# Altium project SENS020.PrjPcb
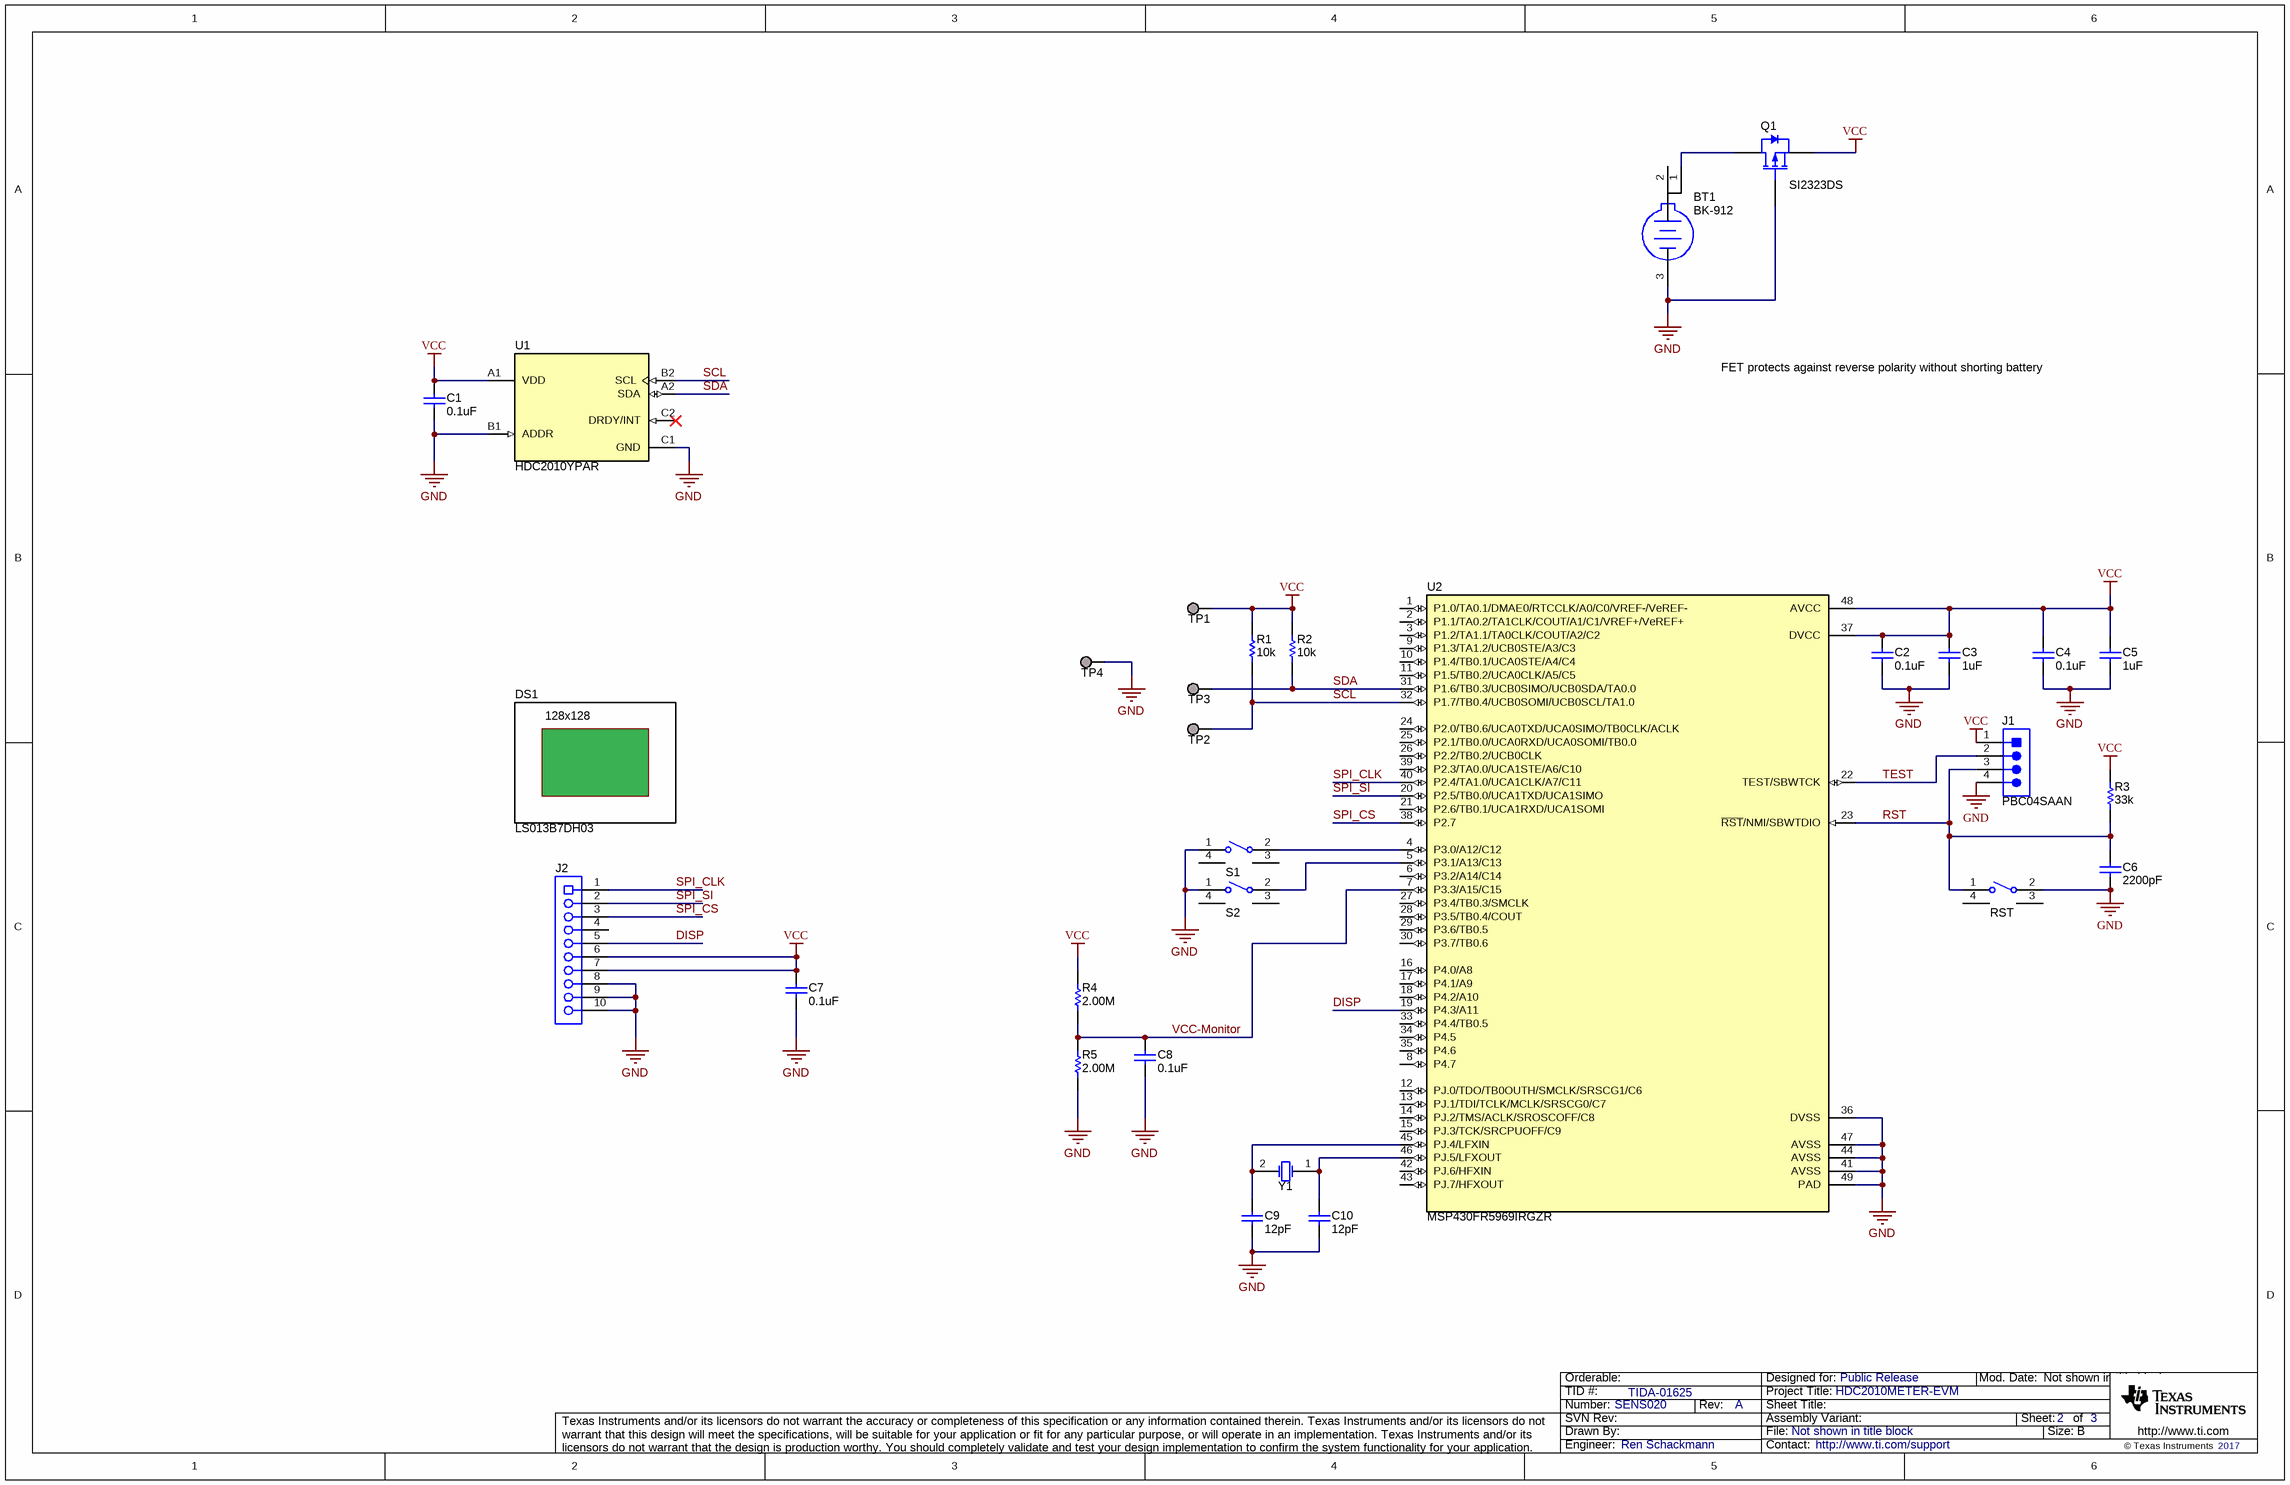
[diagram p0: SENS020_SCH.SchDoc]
TID: TIDA-01625; TechSupport: http://www.ti.com/support; SCH_Rev: A; PRJ_Title: HDC2010METER-EVM; PRJ_Number: SENS020; PRJ_Engineer: Ren Schackmann; PRJ_Customer: Public Release; PCB_Rev: A; PCB_Layout: Ren Schackmann; CopyrightYear: 2017
2 sheets, 51 parts. Net scope: global (net labels, ports and power ports of the same name join across sheets).
Board file: SENS020_PCB.PcbDoc
Sheets:
  SENS020_SCH.SchDoc
  SENS020_Hardware.SchDoc

## Sheet SENS020_SCH.SchDoc
size 431 x 279 mm; Date: Not shown in title block; ApprovedBy: Not shown in title block; CheckedBy: Not shown in title block; Author: Not shown in title block; CompanyName: Not shown in title block; Engineer: Not shown in title block; Organization: Not shown in title block; Address1: Not shown in title block; Address2: Not shown in title block; Address3: Not shown in title block; Address4: Not shown in title block; DocumentNumber: 1; Revision: Use project parameter SCH_Rev; SheetNumber: 2; SheetTotal: 3; PageSetup: Record=PageOptions¦CenterHorizontal=True¦CenterVertical=True¦PrintScale=1.00¦XCorrection=1.00¦YCorrection=1.00¦PrintKind=0¦BorderSize=5000000¦LeftOffset=0¦BottomOffset=0¦Orientation=2¦PaperLength=1000¦PaperWidth=1000¦Scale=100¦PaperSource=15¦PrintQuality=600¦MediaType=1¦DitherType=10¦PaperKind=Letter¦PrintScaleMode=1

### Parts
BT1  BK-912  [MPD_BK-912]
C1  ValueDisplayed: 0.1uF  [0201_033]  (hidden comment: GRM033R61C104KE84D)
C2  ValueDisplayed: 0.1uF  [0402]  (hidden comment: GRM155R61A104KA01D)
C3  ValueDisplayed: 1uF  [0402]  (hidden comment: GRM155R60J105KE19D)
C4  ValueDisplayed: 0.1uF  [0402]  (hidden comment: GRM155R61A104KA01D)
C5  ValueDisplayed: 1uF  [0402]  (hidden comment: GRM155R60J105KE19D)
C6  ValueDisplayed: 2200pF  [0402]  (hidden comment: GRM155R60J222KA01D)
C7  ValueDisplayed: 0.1uF  [0402]  (hidden comment: GRM155R61A104KA01D)
C8  ValueDisplayed: 0.1uF  [0402]  (hidden comment: GRM155R61A104KA01D)
C9  ValueDisplayed: 12pF  [0201]  (hidden comment: GRM0335C1H120JA01D)
C10  ValueDisplayed: 12pF  [0201]  (hidden comment: GRM0335C1H120JA01D)
DS1  LS013B7DH03  [Sharp_LS013B7DH03]
J1  PBC04SAAN  [Sullins_xxC04SAAN]
J2  FH12-10S-0.5SH[55]  [Hirose_FH12-10S-0_5SH[55]]  (value not drawn)
Q1  SI2323DS  [SOT-23]
R1  ValueDisplayed: 10k  [0402]  (hidden comment: CRCW040210K0JNED)
R2  ValueDisplayed: 10k  [0402]  (hidden comment: CRCW040210K0JNED)
R3  ValueDisplayed: 33k  [0402]  (hidden comment: CRCW040233K0JNED)
R4  ValueDisplayed: 2.00M  [0402]  (hidden comment: CRCW04022M00FKED)
R5  ValueDisplayed: 2.00M  [0402]  (hidden comment: CRCW04022M00FKED)
RST  TL3330AF260QG  [SW_TL3330]  (value not drawn)
S1  TL3330AF260QG  [SW_TL3330]  (value not drawn)
S2  TL3330AF260QG  [SW_TL3330]  (value not drawn)
TP1  S2761-46R  [Harwin_S2761-46R]  (value not drawn)
TP2  S2761-46R  [Harwin_S2761-46R]  (value not drawn)
TP3  S2761-46R  [Harwin_S2761-46R]  (value not drawn)
TP4  S2761-46R  [Harwin_S2761-46R]  (value not drawn)
U1  HDC2010YPAR  [YPA0006ABAB]
U2  MSP430FR5969IRGZR  [RGZ0048B]
Y1  ABS07-32.768KHZ-T  [XTAL_ABS07]  (value not drawn)

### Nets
GND: BT1.3(-) C1.2 C2.2 C3.2 C4.2 C5.2 C6.2 C7.2 C8.2 C9.2 C10.2 J1.4 J2.8 J2.9 J2.10 Q1.1(G) R5.1 RST.2 S1.1 S2.1 TP4.1 U1.B1(ADDR) U1.C1(GND) U2.36(DVSS) U2.41(AVSS) U2.44(AVSS) U2.47(AVSS) U2.49(PAD)
VCC: C1.1 C2.1 C3.1 C4.1 C5.1 C7.1 J1.1 J2.6 J2.7 Q1.2(S) R1.2 R2.2 R3.2 R4.2 TP1.1 U1.A1(VDD) U2.37(DVCC) U2.48(AVCC)
DISP: J2.5 U2.19(P4.3/A11)
RST: C6.1 J1.3 R3.1 RST.1 U2.23(~{RST}/NMI/SBWTDIO)
SCL: R1.1 TP2.1 U1.B2(SCL) U2.32(P1.7/TB0.4/UCB0SOMI/UCB0SCL/TA1.0)
SDA: R2.1 TP3.1 U1.A2(SDA) U2.31(P1.6/TB0.3/UCB0SIMO/UCB0SDA/TA0.0)
SPI_CLK: J2.1 U2.40(P2.4/TA1.0/UCA1CLK/A7/C11)
SPI_CS: J2.3 U2.38(P2.7)
SPI_SI: J2.2 U2.20(P2.5/TB0.0/UCA1TXD/UCA1SIMO)
TEST: J1.2 U2.22(TEST/SBWTCK)
VCC-Monitor: C8.1 R4.1 R5.2 U2.7(P3.3/A15/C15)
NetBT1_1: BT1.1(+) Q1.3(D)
NetC9_1: C9.1 U2.45(PJ.4/LFXIN) Y1.2(OSC2)
NetC10_1: C10.1 U2.46(PJ.5/LFXOUT) Y1.1(OSC1)
NetS1_2: S1.2 U2.4(P3.0/A12/C12)
NetS2_2: S2.2 U2.5(P3.1/A13/C13)

Not connected (* = marked no-connect by the designer): BT1 2(+); J2 4; RST 3 4; S1 3 4; S2 3 4; U1 C2(DRDY/INT)*; U2 1(P1.0/TA0.1/DMAE0/RTCCLK/A0/C0/VREF-/VeREF-) 2(P1.1/TA0.2/TA1CLK/COUT/A1/C1/VREF+/VeREF+) 3(P1.2/TA1.1/TA0CLK/COUT/A2/C2) 6(P3.2/A14/C14) 8(P4.7) 9(P1.3/TA1.2/UCB0STE/A3/C3) 10(P1.4/TB0.1/UCA0STE/A4/C4) 11(P1.5/TB0.2/UCA0CLK/A5/C5) 12(PJ.0/TDO/TB0OUTH/SMCLK/SRSCG1/C6) 13(PJ.1/TDI/TCLK/MCLK/SRSCG0/C7) 14(PJ.2/TMS/ACLK/SROSCOFF/C8) 15(PJ.3/TCK/SRCPUOFF/C9) 16(P4.0/A8) 17(P4.1/A9) 18(P4.2/A10) 21(P2.6/TB0.1/UCA1RXD/UCA1SOMI) 24(P2.0/TB0.6/UCA0TXD/UCA0SIMO/TB0CLK/ACLK) 25(P2.1/TB0.0/UCA0RXD/UCA0SOMI/TB0.0) 26(P2.2/TB0.2/UCB0CLK) 27(P3.4/TB0.3/SMCLK) 28(P3.5/TB0.4/COUT) 29(P3.6/TB0.5) 30(P3.7/TB0.6) 33(P4.4/TB0.5) 34(P4.5) 35(P4.6) 39(P2.3/TA0.0/UCA1STE/A6/C10) 42(PJ.6/HFXIN) 43(PJ.7/HFXOUT)

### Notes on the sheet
- FET protects against reverse polarity without shorting battery

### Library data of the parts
BT1 = CMP-0003749-2: Battery Holder for CR2032, SMT; Manufacturer: Memory Protection Devices
C1 = CMP-0009717-2: CAP, CERM, 0.1 uF, 16 V, +/- 10%, X5R, 0201; Manufacturer: MuRata; Polarized: N; Value: 0.1uF; U/M: EA; Cap_F: 100nF; Value1: Unknown; VDC_V: 16V; TaMin_C: -55°C; TaMax_C: 85°C; Cap_Case: 0201; SizeArea_mm2: 0.18; SizeAreaWB_mm2: 2.08; SizeX_mm: 0.6; SizeY_mm: 0.3; SizeZ_mm: 0.33; AEC Category: Q200
C2 C4 C7 C8 = CMP-0006562-2: CAP, CERM, 0.1 uF, 10 V, +/- 10%, X5R, 0402; Manufacturer: MuRata; Polarized: N; Value: 0.1uF; U/M: EA; Cap_F: 100nF; Value1: Unknown; VDC_V: 10V; TaMin_C: -55°C; TaMax_C: 85°C; SizeArea_mm2: 0.5; SizeAreaWB_mm2: 3; SizeX_mm: 1; SizeZ_mm: 0.6; AEC Category: Q200
C3 C5 = CMP-0006532-2: CAP, CERM, 1 uF, 6.3 V, +/- 10%, X5R, 0402; Manufacturer: MuRata; Polarized: N; Value: 1uF; U/M: EA; Cap_F: 1µF; Value1: Unknown; VDC_V: 6.3V; TaMin_C: -55°C; TaMax_C: 85°C; SizeArea_mm2: 0.5; SizeAreaWB_mm2: 3; SizeX_mm: 1; SizeZ_mm: 0.6; AEC Category: Q200
C6 = CMP-0006540-2: CAP, CERM, 2200 pF, 6.3 V, +/- 10%, X5R, 0402; Manufacturer: MuRata; Polarized: N; Value: 2200pF; U/M: EA; Cap_F: 2.2nF; Value1: Unknown; VDC_V: 6.3V; TaMin_C: -55°C; TaMax_C: 85°C; AEC Category: Q200; SizeArea_mm2: 0.5; SizeAreaWB_mm2: 3; SizeX_mm: 1; SizeZ_mm: 0.6
C9 C10 = CMP-0009664-3: CAP, CERM, 12 pF, 50 V, +/- 5%, C0G/NP0, 0201; Manufacturer: MuRata; Polarized: N; Value: 12pF; U/M: EA; Value1: Unknown; VDC_V: 50V; TaMin_C: -55°C; TaMax_C: 125°C; SizeArea_mm2: 0.18; SizeAreaWB_mm2: 2.08; SizeX_mm: 0.6; SizeY_mm: 0.3; SizeZ_mm: 0.26; AEC Category: Q200
DS1 = CMP-0067626-1: LCD Display Dot Pixels 128x128; Manufacturer: Sharp Microelectronics; CompType: LCD Module
J1 = CMP-0054583-1: Header, 2.54 mm, 4x1, Gold, TH; Manufacturer: Sullins Connector Solutions; Pitch_mm: 2.54; Gender: Male; Shrouded: N; Row_Count: 1; Current_A: 3A; Voltage_V: 1.8kV; Cert_UL: Y; CNHeader: TRUE; CT: FALSE; Green_Lifecycle: Not Set; Green_REACh: Incomplete
J2 = CMP-0075009-2: Connector, FPC 10 Pos. 9.1x2.0x5.6 mm; PartNumber: FH12-10S-0.5SH(55); Manufacturer: Hirose Electric Co. Ltd.; CompType: FFC or FPC; CNHeader: False; CT: True
Q1 = CMP-0000092-2: MOSFET, P-CH, -20 V, -3.7 A, SOT-23; Manufacturer: Vishay-Siliconix; Alternate Manufacturer: None; U/M: EA; ChType: P; Value: -20V; Value1: 0.03; Rdson45_ohm: 0.031; Value2: 12.5 nC; QgTyp_nC: 12.5; Vgs_V: -8V; IdsMax_A: -3.7A; SizeAreaWB_mm2: 14; SizeArea_mm2: 7.5; SizeX_mm: 2.5; SizeY_mm: 3; SizeZ_mm: 1.1; AEC Category: Q101
R1 R2 = CMP-0026825-4: RES, 10 k, 5%, 0.063 W, 0402; Manufacturer: Vishay-Dale; Value: 10k; Value_Code: 10k0; Power_W: 63mW; Value2: 0.063W; VDC_V: 50V; TempCo: 200 ppm/C; SizeArea_mm2: 0.5; SizeX_mm: 1; SizeZ_mm: 0.6; EIA_Code: E24; U/M: EA; AEC Category: Q200
R3 = CMP-0026907-2: RES, 33 k, 5%, 0.063 W, 0402; Manufacturer: Vishay-Dale; Value: 33k; Value_Code: 33k0; Power_W: 63mW; Value2: 0.063W; VDC_V: 50V; TempCo: 200 ppm/C; EIA_Code: E24; U/M: EA; AEC Category: Q200; SizeArea_mm2: 0.5; SizeX_mm: 1; SizeZ_mm: 0.6
R4 R5 = CMP-0026245-1: RES, 2.00 M, 1%, 0.063 W, 0402; Manufacturer: Vishay-Dale; Value: 2.00Meg; Res_ohm: 2M; Value_Code: 2M00; Power_W: 63mW; Value2: 0.063W; VDC_V: 50V; TempCo: 100 ppm/C; SizeArea_mm2: 0.5; SizeX_mm: 1; SizeZ_mm: 0.6; EIA_Code: E96; U/M: EA; AEC Category: Q200
RST S1 S2 = CMP-0002231-1: Switch, SPST-NO,  1 Pos, 0.05A, 12VDC, SMD; Manufacturer: E-Switch; VDC_V: 12V; SwitchFunction: Off-Mom; PositionCount: 1; CurrentRating_mA: 50A
TP1-TP4 = CMP-0067619-1: Natural PC Test Point Brass, SMT; Manufacturer: Harwin
U1 = CMP-0014223-2: HDC2010 Low Power Humidity and Temperature Digital Sensor, YPA0006ABAB (DSBGA-6); Alternate PartNumber: HDC2010YPAT; Manufacturer: Texas Instruments; SizeArea_mm2: 2.1316; SizeAreaWB_mm2: 6.0516; SizeX_mm: 1.46; SizeZ_mm: 0.675; CompType: IC; U/M: EA
U2 = CMP-0066503-2: MSP430FR5969 16 MHz Ultra-Low-Power Microcontroller featuring 64 KB FRAM, 2 KB SRAM, 40 IO, RGZ0048B (VQFN-48); Alternate PartNumber: MSP430FR5969IRGZT; Manufacturer: Texas Instruments; SizeArea_mm2: 49; SizeAreaWB_mm2: 81; SizeX_mm: 7; SizeZ_mm: 1; CompType: IC; U/M: EA; Green_Lifecycle: Active; Green_REACh: Passed
Y1 = CMP-0004628-3: CRYSTAL, 32.768KHz, 12.5PF, SMD; Manufacturer: Abracon Corporation; TaMin_C: -40°C; TaMax_C: 85°C; Frequency Stability: +/-20ppm

## Sheet SENS020_Hardware.SchDoc
size 431 x 279 mm; Date: Not shown in title block; ApprovedBy: Not shown in title block; CheckedBy: Not shown in title block; Author: Not shown in title block; CompanyName: Not shown in title block; Engineer: Not shown in title block; Organization: Not shown in title block; Address1: Not shown in title block; Address2: Not shown in title block; Address3: Not shown in title block; Address4: Not shown in title block; DocumentNumber: 1; Revision: Use project parameter SCH_Rev; SheetNumber: 3; SheetTotal: 3; PageSetup: Record=PageOptions¦CenterHorizontal=True¦CenterVertical=True¦PrintScale=1.00¦XCorrection=1.00¦YCorrection=1.00¦PrintKind=0¦BorderSize=5000000¦LeftOffset=0¦BottomOffset=0¦Orientation=2¦PaperLength=1000¦PaperWidth=1000¦Scale=100¦PaperSource=15¦PrintQuality=600¦MediaType=1¦DitherType=10¦PaperKind=Letter¦PrintScaleMode=1
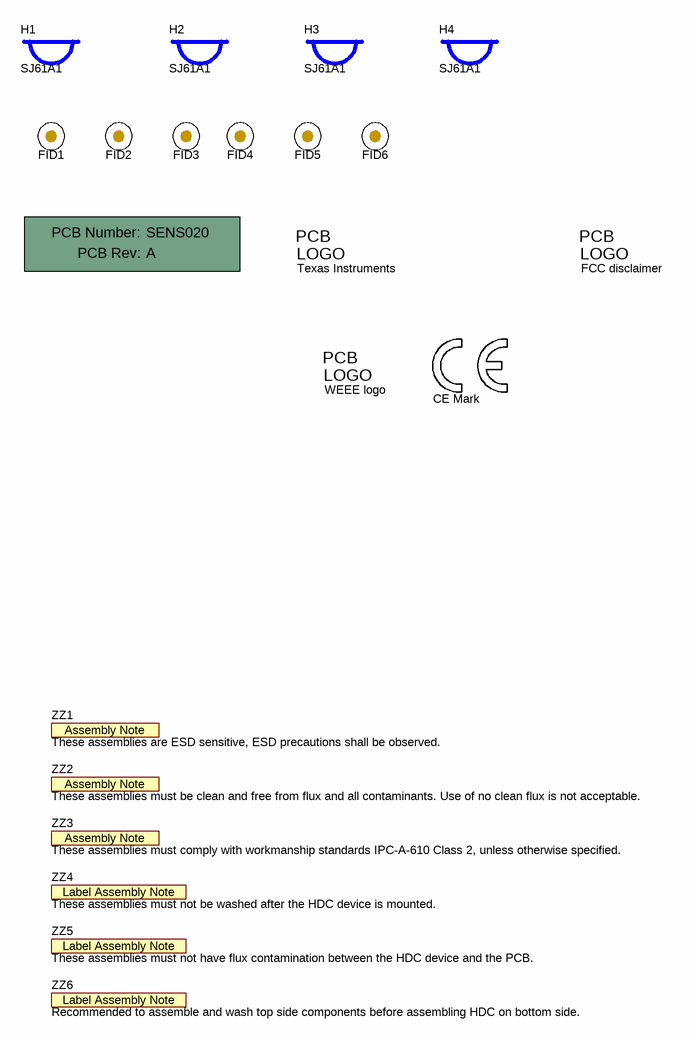
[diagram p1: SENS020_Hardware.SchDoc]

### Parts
!PCB1  Printed Circuit Board  (value not drawn)  (mechanical)
FID1  Fiducial  [Fiducial10-20]  (value not drawn)  (no BOM)
FID2  Fiducial  [Fiducial10-20]  (value not drawn)  (no BOM)
FID3  Fiducial  [Fiducial10-20]  (value not drawn)  (no BOM)
FID4  Fiducial  [Fiducial10-20]  (value not drawn)  (no BOM)
FID5  Fiducial  [Fiducial10-20]  (value not drawn)  (no BOM)
FID6  Fiducial  [Fiducial10-20]  (value not drawn)  (no BOM)
H1  SJ61A1  [Bumpon_SJ61A1]
H2  SJ61A1  [Bumpon_SJ61A1]
H3  SJ61A1  [Bumpon_SJ61A1]
H4  SJ61A1  [Bumpon_SJ61A1]
Logo1  Texas Instruments  [TI_Stacked_Overlay_Small]  (no BOM)
LOGO2  CE Mark  [CE_Mark_5mm]  (no BOM)
Logo3  FCC disclaimer  [FCC_disclaimer]  (no BOM)
Logo4  WEEE logo  [WEEE_Minimum]  (no BOM)
ZZ1  These assemblies are ESD sensitive, ESD precautions shall be observed.  [AssemblyNote]  (no BOM)
ZZ2  These assemblies must be clean and free from flux and all contaminants. Use of no clean flux is not acceptable.  [AssemblyNote]  (no BOM)
ZZ3  These assemblies must comply with workmanship standards IPC-A-610 Class 2, unless otherwise specified.  [AssemblyNote]  (no BOM)
ZZ4  These assemblies must not be washed after the HDC device is mounted.  [AssemblyNoteLabel]  (no BOM)
ZZ5  These assemblies must not have flux contamination between the HDC device and the PCB.  [AssemblyNoteLabel]  (no BOM)
ZZ6  Recommended to assemble and wash top side components before assembling HDC on bottom side.  [AssemblyNoteLabel]  (no BOM)

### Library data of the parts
!PCB1 = CMP-0003618-2: Manufacturer: Any; PartNumber: SENS020
FID1-FID6 = CMP-0077181-1: Fiducial mark.  There is nothing to buy or mount.
H1-H4 = CMP-0003621-1: Bumpon, Cylindrical, 0.312 X 0.200, Black; Manufacturer: 3M
Logo1 = CMP-0074838-1: Texas Instrument Corporate Signature; SymbolCreator: a0412235; Lib Reference: TI_Logo; Library Reference: Logo
LOGO2 = CMP-0074844-1: SymbolCreator: a0412235
Logo3 = CMP-0074847-1: FCC_disclaimer; Library Reference: Logo
Logo4 = CMP-0074769-1
ZZ1 = CMP-0077236-1
ZZ2 = CMP-0077237-1
ZZ3 = CMP-0077238-1
ZZ4-ZZ6 = CMP-0003616-3: This Assembly Note is for PCB labels only

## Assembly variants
001: not fitted C8 J1 R4 R5
Hide-Disp: not fitted DS1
